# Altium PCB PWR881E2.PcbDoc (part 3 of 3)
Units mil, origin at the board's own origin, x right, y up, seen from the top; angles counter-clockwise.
Board outline 6500 x 3500 mil, 6 copper layers (Top Layer, Signal Layer 1, Signal Layer 2, Signal Layer 3, Signal Layer 4, Bottom Layer), stack 32.4 mil thick; 330 components, 152 nets, 836 pads, 570 vias.
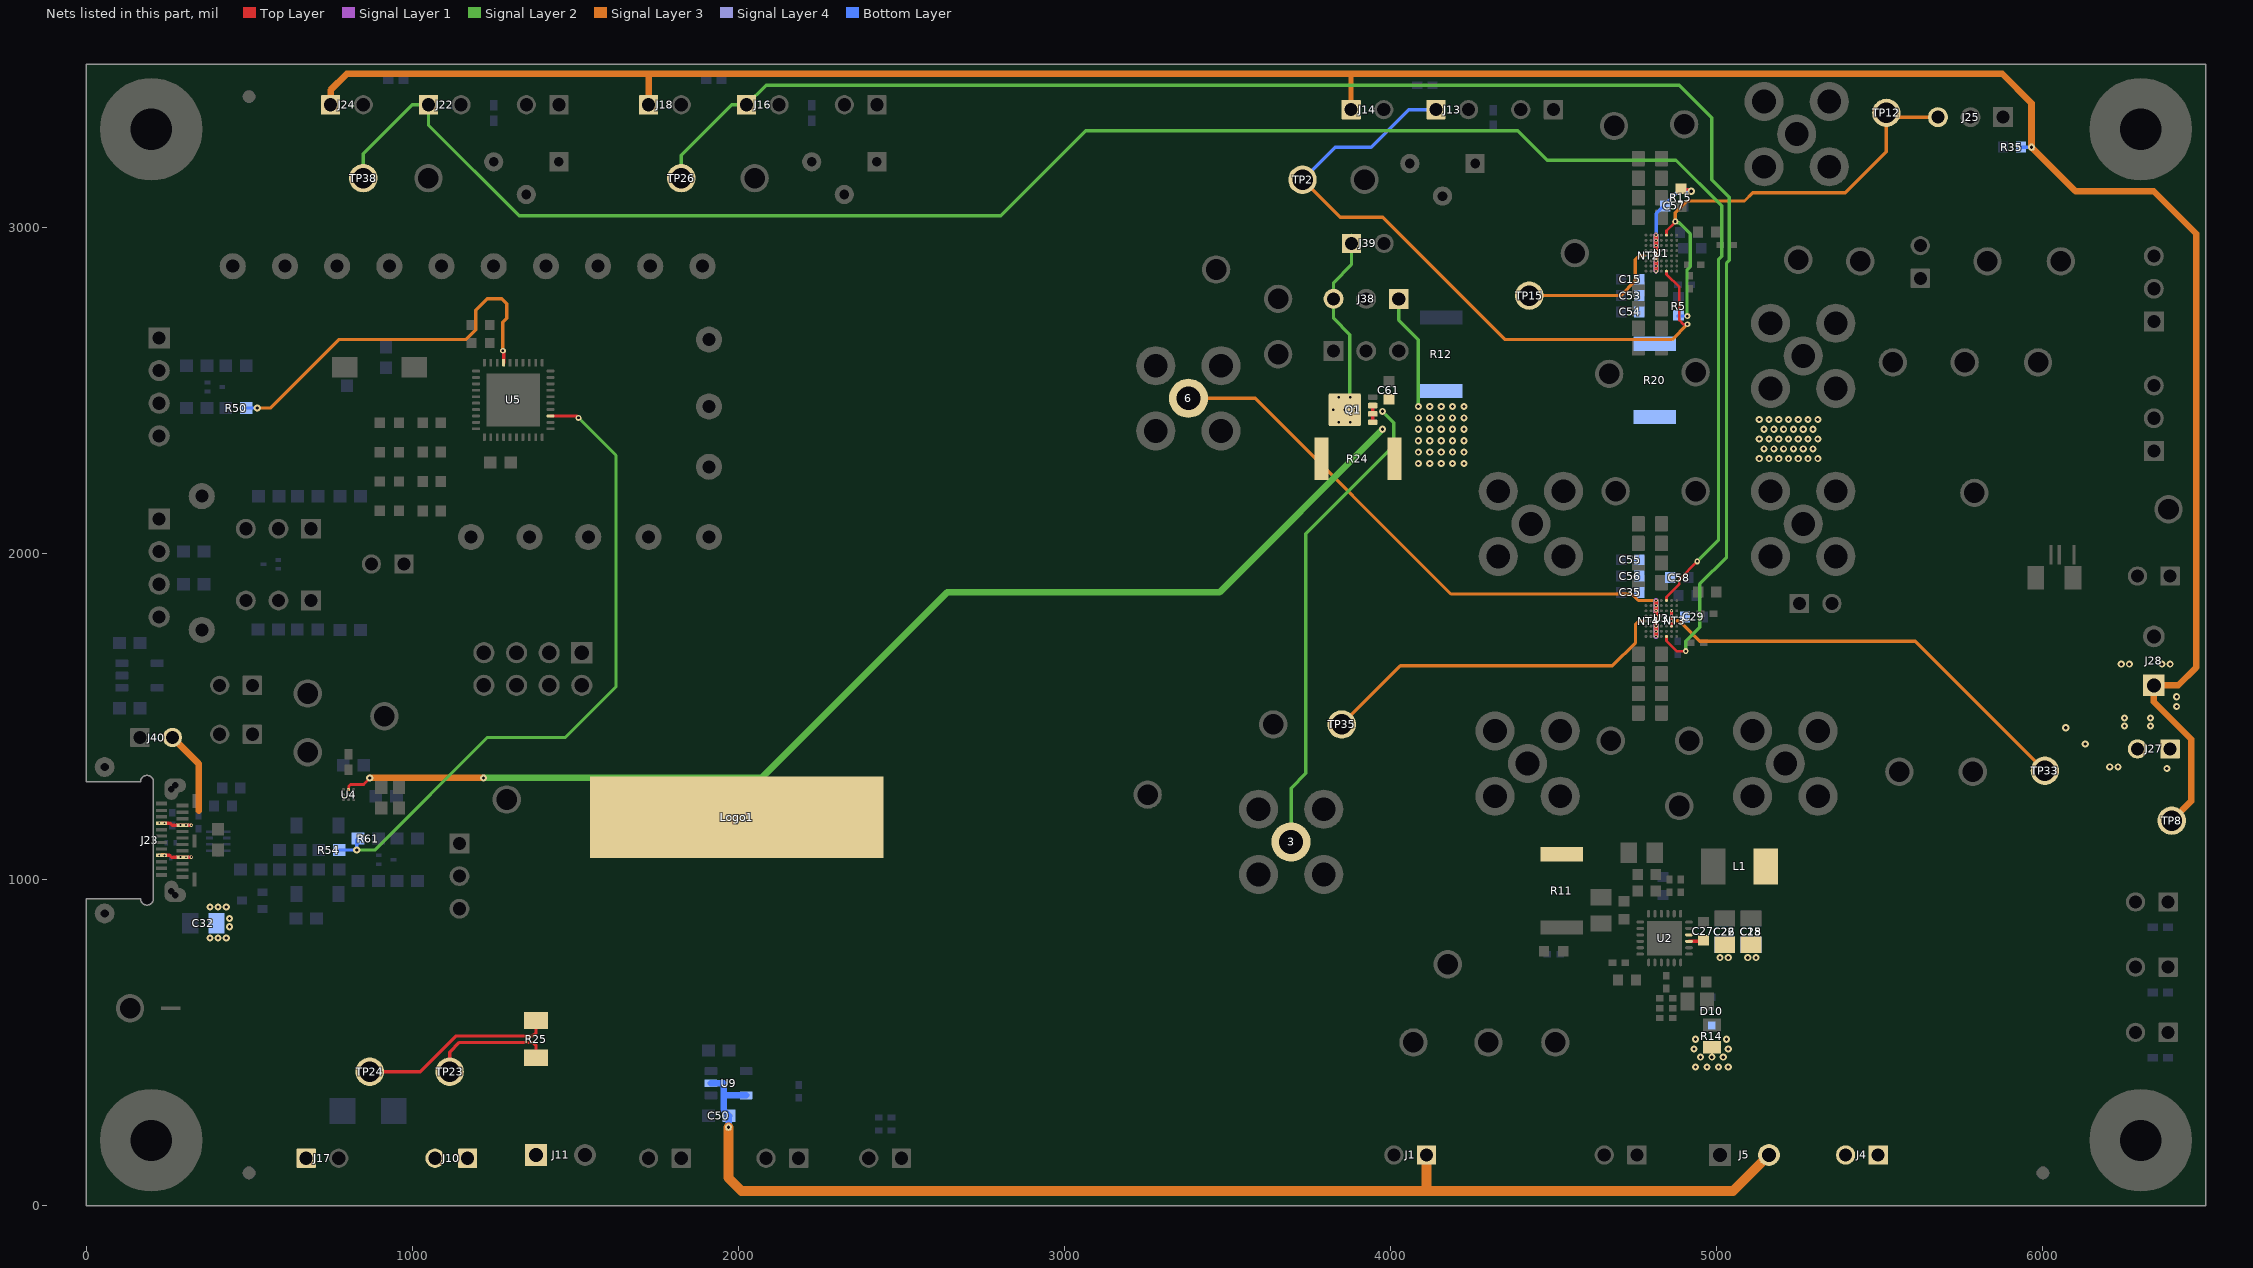
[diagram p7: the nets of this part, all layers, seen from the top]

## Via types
v1: diameter 22, hole 10, Top Layer to Bottom Layer, tented both sides, 399 vias
v2: diameter 10, hole 6, Top Layer to Bottom Layer, tented both sides, 72 vias
v3: diameter 18, hole 8, Top Layer to Bottom Layer, tented both sides, 37 vias
v4: diameter 28, hole 12, Top Layer to Bottom Layer, tented both sides, 36 vias
v5: diameter 19.68, hole 7.87, Top Layer to Bottom Layer, 23 vias
v6: diameter 12, hole 6, Top Layer to Bottom Layer, tented both sides, 2 vias
v7: diameter 19.68, hole 7.87, Top Layer to Bottom Layer, tented both sides, 1 vias

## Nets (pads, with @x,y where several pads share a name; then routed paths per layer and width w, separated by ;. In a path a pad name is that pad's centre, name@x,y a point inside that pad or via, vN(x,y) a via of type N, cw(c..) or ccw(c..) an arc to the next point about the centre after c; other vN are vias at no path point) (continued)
SYNCOUT: J25.3 R5.2 TP12.1 U1.A5 | length 1423.8
  Top Layer w8: U1.A5@4845.75,2975.12 4845.75,2988.75 4868.5,3011.5 v3@4868.5,3017.5
  Signal Layer 2 w10: v3@4869,3017 4876,3017 4880,3013 4885,3013 4919,2979 4919,2879 4909,2869 v3@4909,2727
  Signal Layer 3 w10: v3@4869,3017 4873,3021 4873,3044 4909,3080 5085,3080 5110,3105 5394,3105 5520,3231 5520,3339 5522,3337 J25.3@5678,3337
  Bottom Layer w10: R5.2@4880,2727.44 4880.44,2727 v3(4910,2727)
  other v3: 4873,3017
SYS: C18.1 C22.1 C25.1 C26.1 C27.1 C50.1 J1.1 J4.1 J4.2 J5.2 L1.2 U2.15 U2.16 U9.2 U9.5 | length 3810.9
  Top Layer w10: U2.15@4914.8,810.16 C27.1@4960,810.16
  Signal Layer 3 w30: v1(1970,240) 1970,85 2010,45 4110,45 ; J1.1@4110,155 4110,45 ; J5.2@5160,155 5050,45 4110,45
  Bottom Layer w20: U9.2@1915.87,375 1955,375 1955,337.6 ; v1(1970,240) C50.1@1970,273.5 ; C50.1@1971.5,275 1955,291.5 1955,337.6 ; U9.5@2024.13,337.6 1955,337.6
  other v1: 5010,760 5035,760 5095,760 5120,760
TEST_MCU: R50.1 U5.37 | length 1166.5
  Top Layer w10: U5.37@1280.47,2584.17 v3@1280.47,2621
  Signal Layer 3 w10: v1@525,2440 530,2445 565,2445 775,2655 1165,2655 1195,2685 1195,2745 1230,2780 1275,2780 1290,2765 1290,2720 1278,2708 v3(1278,2621)
  Bottom Layer w10: R50.1@491.5,2445 v1(525,2445)
TSBAT_S: J22.1 TP38.1 U3.A5 | length 5962.2
  Top Layer w8: U3.A5@4845.75,1855.12 4845.75,1865.75 4885,1905 4885,1920 v3(4940,1975)
  Signal Layer 2 w10: TP38.1@850,3150 850,3225 1000,3375 J22.1@1050,3375 1050,3313 1328,3035 2805,3035 3065,3295 4390,3295 4480,3205 4875,3205 5015,3065 5015,2910 5005,2900 5005,2040 v3(4940,1975)
TSBUS_M: J13.1 TP2.1 U1.H5 | length 2097
  Top Layer w8: U1.H5@4845.75,2864.88 4845.75,2855.25 4885,2816 4885,2715 4898,2702 v3(4910,2702)
  Signal Layer 3 w10: TP2.1@3730,3145 3845,3030 3976,3030 4351,2655 4863,2655 v3(4910,2702)
  Bottom Layer w10: TP2.1@3730,3145 3830,3245 3940,3245 4055,3360 J13.1@4139,3360
TSBUS_S: J16.1 TP26.1 U3.H5 | length 5193.7
  Top Layer w8: U3.H5@4845.75,1744.88 4845.75,1731.25 4877,1700 v3(4905,1700)
  Signal Layer 2 w10: TP26.1@1825,3150 1850,3150 1825,3175 1825,3220 1980,3375 J16.1@2025,3375 2085,3435 4885,3435 4985,3335 4985,3145 5038,3092 5038,2898 5030,2890 5030,1988 4948,1906 4948,1773 4905,1730 v3(4905,1700)
TX_MCU: R54.2 R61.1 U5.23 | length 2045.8
  Top Layer w10: U5.23@1424.17,2420.79 1504.21,2420.79 v3@1505,2420
  Signal Layer 2 w10: v1(830,1090) 885,1090 1230,1435 1470,1435 1625,1590 1625,2300 v3(1510,2415)
  Bottom Layer w10: R54.2@776.5,1090 v1(830,1090) 830,1121.5 R61.1@833.5,1125
VBUS_C: C32.1 J17.1 J23.A4 J23.A9 J23.B4 J23.B9 J38.3 J39.1 J40.2 Logo1.0 Q1.5 Q1.6 Q1.7 Q1.8 Q1.9@3859.41,2440 R24.1 R25.1 TP24.1 | length 1601.6
  Top Layer w10: J23.B4@231.3,1073.74 v2(241.3,1073.74) 256.26,1073.74 262.17,1067.83 J23.A9@296.26,1067.83 296.43,1068 v2(323,1068) ; J23.B9@231.3,1172.17 257.83,1172.17 263.74,1166.26 J23.A4@296.26,1166.26 296.52,1166 v2(323,1166) ; TP24.1@870,410 1025,410 1135,520 1370,520 1380,530 R25.1@1380,567.09
  Signal Layer 2 w10: v5@3878.1,2478.39 3875,2481.49 3875,2670 3825,2720 3825,2830 3880,2885 J39.1@3880,2975
  Signal Layer 3 w10: v2(224.54,1073.91) 224.7,1073.74 v2(241.3,1073.74)
  Signal Layer 3 w20: J40.2@265,1435 345,1355 345,1210
  other v1: 380,820 405,820 430,820 440,855 440,880 380,915 405,915 430,915
  other v2: 289.5,1068 306.26,1067.83 289.5,1166.43 306.26,1166.26 224.54,1172.33 241.3,1172.17
  other v5: 3841.61,2401.61 3876.1,2401.61 3858.86,2440 3893.35,2440 3841.61,2478.39 3876.1,2478.39
  other v7: 3824.37,2440
VBUS_CHG: 3.1 C29.2 C61.1 J38.1 NT3.1 Q1.1 Q1.2 Q1.3 R11.2 R12.2 R24.2 U3.C6 U3.D6 U3.E6 U3.F6 U4.A2 | length 5551.4
  Top Layer w8: U4.A2@805,1275.75 805,1285 811,1291 851,1291 v1@870.5,1310.5
  Top Layer w10: Q1.1@3945.04,2401.61 Q1.2@3945.04,2427.2 Q1.3@3945.04,2452.8 ; U3.F6@4861.5,1776.38 v2(4861.5,1792.13) v2(4861.5,1807.87) v2(4861.5,1823.62)
  Signal Layer 2 w10: 3.1@3695,1115 3695,1280 3740,1325 3740,2060 4010,2330 4010,2400 v1(3975,2435) ; J38.1@4025,2780 4025,2715 4085,2655 v1(4085,2450)
  Signal Layer 2 w20: v1(1219,1311) 2071,1311 2640,1880 3475,1880 v1(3975,2380)
  Signal Layer 3 w20: v1(870,1311) v1(1219,1311)
  other v1: 4085,2275 4120,2275 4155,2275 4190,2275 4225,2275 4085,2310 4120,2310 4155,2310 4190,2310 4225,2310 4085,2345 4120,2345 4155,2345 4190,2345 4225,2345 4085,2380 4120,2380 4155,2380 4190,2380 4225,2380 4085,2415 4120,2415 4155,2415 4190,2415 4225,2415 4120,2450 4155,2450 4190,2450 4225,2450
VBUS_CHG_SNS: NT3.2 TP33.1 | length 1318.5
  Signal Layer 3 w10: NT3.2@4878,1793 4885,1793 4948,1730 5609,1730 TP33.1@6006,1333
VBUS_P: J10.1 J10.2 J11.1 R25.2 TP23.1 | length 388.7
  Top Layer w10: TP23.1@1115,400 1115,470 1145,500 1370,500 1380,490 R25.2@1380,452.91
VOUT: 6.1 C35.1 C55.1 C56.1 C58.1 D10.1 J14.1 J18.1 J24.1 J27.1 J27.2 J28.1 NT4.1 R14.2 R20.2 R35.1 TP8.1 U3.A3 U3.B3 U3.C3 U3.D3 U3.E3 U3.F3 U3.G3 U3.H3 | length 10617.7
  Top Layer w10: v2(4814.25,1744.88) v2(4814.25,1760.63) v2(4814.25,1776.38) v2(4814.25,1792.13) v2(4814.25,1807.87) v2(4814.25,1823.62) v2(4814.25,1839.37) v2(4814.25,1855.12)
  Signal Layer 1 w15: v2(4814.25,1744.88) v2(4814.25,1760.63) v2(4814.25,1776.38) v2(4814.25,1792.13) v2(4814.25,1807.87) v2(4814.25,1823.62) v2(4814.25,1839.37) v2(4814.25,1855.12)
  Signal Layer 2 w15: v2(4814.25,1744.88) v2(4814.25,1760.63) v2(4814.25,1776.38) v2(4814.25,1792.13) v2(4814.25,1807.87) v2(4814.25,1823.62) v2(4814.25,1839.37) v2(4814.25,1855.12)
  Signal Layer 3 w10: 6.1@3380,2475 3585,2475 4185,1875 4740,1875 4759.88,1855.12 v2(4814.25,1855.12) ; 3879,3469 3880,3470
  Signal Layer 3 w15: J14.1@3879,3360 3879,3469 ; v2(4814.25,1744.88) v2(4814.25,1760.63) v2(4814.25,1776.38) v2(4814.25,1792.13) v2(4814.25,1807.87) v2(4814.25,1823.62) v2(4814.25,1839.37) v2(4814.25,1855.12)
  Signal Layer 3 w20: J24.1@750,3375 750,3420 800,3470 1725,3470 ; J18.1@1725,3375 1725,3470 ; J28.1@6330,1585 6340,1585 6340,1545 6455,1430 6455,1240 TP8.1@6395,1180 ; J28.1@6340,1595 6415,1595 6470,1650 6470,2980 ; 6462.5,2987.5 6340,3110 6100,3110 v1(5965,3245) 5965,3380 5875,3470 3880,3470 1725,3470
  Signal Layer 4 w15: v2(4814.25,1744.88) v2(4814.25,1760.63) v2(4814.25,1776.38) v2(4814.25,1792.13) v2(4814.25,1807.87) v2(4814.25,1823.62) v2(4814.25,1839.37) v2(4814.25,1855.12)
  Bottom Layer w10: v2(4814.25,1744.88) v2(4814.25,1760.63) v2(4814.25,1776.38) v2(4814.25,1792.13) v2(4814.25,1807.87) v2(4814.25,1823.62) v2(4814.25,1839.37) v2(4814.25,1855.12) ; R35.1@5932.56,3245 v1(5965,3245)
  other v1: 4935,425 4970,425 5005,425 5035,425 4950,455 4985,455 5020,455 4930,480 5035,480 4935,510 5030,510 6380,1340 6205,1345 6230,1345 6130,1415 6070,1465 6250,1470 6330,1470 6250,1495 6330,1495 6410,1530 6410,1560 6240,1660 6265,1660 6365,1660 6390,1660 5130,2290 5160,2290 5190,2290 5220,2290 5250,2290 5280,2290 5310,2290 5145,2320 5175,2320 5205,2320 5235,2320 5265,2320 5295,2320 5130,2350 5160,2350 5190,2350 5220,2350 5250,2350 5280,2350 5310,2350 5145,2380 5175,2380 5205,2380 5235,2380 5265,2380 5295,2380 5130,2410 5160,2410 5190,2410 5220,2410 5250,2410 5280,2410 5310,2410
VOUT_M: C15.1 C53.1 C54.1 C57.1 NT2.1 R15.2 R20.1 U1.A3 U1.B3 U1.C3 U1.D3 U1.E3 U1.F3 U1.G3 U1.H3 | length 897.2
  Top Layer w10: v2(4814.25,2864.88) v2(4814.25,2880.63) v2(4814.25,2896.38) v2(4814.25,2912.13) v2(4814.25,2927.87) v2(4814.25,2943.62) v2(4814.25,2959.37) v2(4814.25,2975.12) ; R15.2@4890,3117.56 4892.56,3115 v1@4922,3115
  Signal Layer 1 w15: v2(4814.25,2864.88) v2(4814.25,2880.63) v2(4814.25,2896.38) v2(4814.25,2912.13) v2(4814.25,2927.87) v2(4814.25,2943.62) v2(4814.25,2959.37) v2(4814.25,2975.12)
  Signal Layer 2 w15: v2(4814.25,2864.88) v2(4814.25,2880.63) v2(4814.25,2896.38) v2(4814.25,2912.13) v2(4814.25,2927.87) v2(4814.25,2943.62) v2(4814.25,2959.37) v2(4814.25,2975.12)
  Signal Layer 3 w15: v2(4814.25,2864.88) v2(4814.25,2880.63) v2(4814.25,2896.38) v2(4814.25,2912.13) v2(4814.25,2927.87) v2(4814.25,2943.62) v2(4814.25,2959.37) v2(4814.25,2975.12)
  Signal Layer 4 w15: v2(4814.25,2864.88) v2(4814.25,2880.63) v2(4814.25,2896.38) v2(4814.25,2912.13) v2(4814.25,2927.87) v2(4814.25,2943.62) v2(4814.25,2959.37) v2(4814.25,2975.12)
  Bottom Layer w10: v2(4814.25,2864.88) v2(4814.25,2880.63) v2(4814.25,2896.38) v2(4814.25,2912.13) v2(4814.25,2927.87) v2(4814.25,2943.62) v2(4814.25,2959.37) v2(4814.25,2975.12) 4814.25,3041.81 4882.44,3110 v1(4922,3110)
VOUT_SNS_M: NT2.2 TP15.1 | length 442.7
  Signal Layer 3 w10: TP15.1@4425,2785 4430,2790 4705,2790 4750,2835 4750,2900 4762,2912 NT2.2@4777,2912
VOUT_SNS_S: NT4.2 TP35.1 | length 1091.1
  Signal Layer 3 w10: TP35.1@3850,1475 4030,1655 4680,1655 4751,1726 4751,1782 4761,1792 NT4.2@4777,1792
pads on no net: FID1.1 FID2.1 FID3.1 FID4.1 FID5.1 FID6.1 H1.0 H2.1 H3.0 H4.1 H5.0 H6.1 H7.0 H8.1 J23.1 J23.2 J23.3 J23.A2 J23.A3 J23.A8 J23.A10 J23.A11 J23.B2 J23.B3 J23.B8 J23.B10 J23.B11 J23.H1 J23.H2 J23.H3 J23.H4 J23.H5 J23.H6 J36.4 LBL1.0 Q1.9@3838.74,2401.61 Q1.9@3838.74,2427.2 Q1.9@3838.74,2452.8 Q1.9@3838.74,2478.39 Q1.9@3858.86,2413.92 Q1.9@3858.86,2466.08 Q1.9@3872.11,2440 Q1.9@3893.35,2413.92 Q1.9@3893.35,2466.08 R29.1 R32.1 R38.1 SH-J1.0 SH-J6.0 SH-J9.0 SH-J16.0 SH-J17.0 SH-J18.0 SH-J19.0 SH-J20p.0 SH-J20s.0 SH-J21p.0 SH-J21s.0 SH-J22.0 SH-J24.0 SH-J26.0 SH-J30.0 SH-J31.0 SH-J37p.0 SH-J37s.0 SH-J38p.0 SH-J38s.0 SH-J39.0 SH-J40.0 SH-J41.0 SH-J42.0 SH-J43.0 U5.41@1256.06,2416.06 U5.41@1256.06,2470 U5.41@1256.06,2523.94 U5.41@1310,2416.06 U5.41@1310,2470 U5.41@1310,2523.94 U5.41@1363.94,2416.06 U5.41@1363.94,2470 U5.41@1363.94,2523.94

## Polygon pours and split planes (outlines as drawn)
GND on Top Layer "TOP_LAYER_GND_P221" (solid, remove dead copper, pour order 352): 25,3475 6475,3475 6475,25 25,25
3V3_SYS on Top Layer "Top Layer-No Net" (solid, remove dead copper, pour order 335): 1235,2575 1235,2615 1235,2625 1230,2630 1225,2635 1225,2715 1225,2750 1235,2760 1245,2760 1260,2760 1265,2755 1265,2715 1265,2575
VBUS_P on Top Layer "Top Layer-No Net" (solid, remove dead copper, pour order 347): 1255,480 1255,415 1210,370 1015,175 1015,90 1450,90 1450,440 1450,480
VBUS_C on Top Layer "Top Layer-No Net" (solid, remove dead copper, pour order 351): 1415,540 1070,540 910,540 725,355 725,110 595,110 410,295 340,365 340,655 340,820 340,940 460,940 520,940 755,940 792.5,977.5 1167.5,977.5 2480,2290 3535,2290 3575,2330 3575,2500 3915,2500 3915,1880 3385,1350 3005,1350 2195,540
VBUS_CHG on Top Layer "Top Layer-No Net" (solid, remove dead copper, pour order 349): 4260,2500 3930,2500 3930,1045 4055,920 4595,920 4595,965 4595,1117.5 4312.5,1117.5 4260,1170
NetC2_1 on Top Layer "Top Layer-No Net" (solid, remove dead copper, pour order 336): 4785,1110 4785,910 4795,900 4820,900 4825,905 4835,915 4835,1110
NetC11_2 on Top Layer "Top Layer-No Net" (solid, remove dead copper, pour order 342): 4865,890 4865,915 4870,920 4875,925 4875,945 4875,975 4900,975 4910,985 4920,995 4920,1010 4920,1065 4950,1095 5030,1095 5030,985 5000,985 4905,890
SYS on Top Layer "Top Layer-No Net" (solid, remove dead copper, pour order 348): 4910,815 4910,835 4955,835 4975,835 4980,840 5000,840 5140,840 5145,845 5150,850 5150,860 5150,900 5150,925 5130,945 5110,965 5110,1095 5220,1095 5257.5,1057.5 5310,1005 5310,770 5535,545 5535,200 5535,140 5535,105 5165,105 5065,105 5065,240 5065,525 5055,535 5030,560 5030,575 5030,705 4935,800 4930,805 4910,805
NetC10_1 on Top Layer "Top Layer-No Net" (solid, remove dead copper, pour order 341): 4905,795 4930,795 5020,705 5020,675 5020,535 4940,535 4940,720 4905,755
Net1_1 on Top Layer "Top Layer-No Net" (solid, remove dead copper, pour order 339): 4810,2915.45 4860,2915.45 4860,2605 4800,2605 4800,2845 4810,2855
NetC13_2 on Top Layer "Top Layer-No Net" (solid, remove dead copper, pour order 344): 4730,2880.45 4730,2603.8 4805,2603.8 4805,2910.45 4805,2915.45 4765,2915.45
NetC14_2 on Top Layer "Top Layer-No Net" (solid, remove dead copper, pour order 343): 4730,3235 4730,2925 4805.42,2925 4800,3186.2 4800,3235
Net2_1 on Top Layer "Top Layer-No Net" (solid, remove dead copper, pour order 337): 4800,3235 4860,3235 4860,2925 4810,2925 4810,3015 4800,3025
Net5_1 on Top Layer "Top Layer-No Net" (solid, remove dead copper, pour order 340): 4800,2119 4860,2119 4860,1805 4840,1805 4810,1805 4810,1870 4800,1880
Net8_1 on Top Layer "Top Layer-No Net" (solid, remove dead copper, pour order 346): 4730,2119 4730,1805 4805,1805 4805,2045 4805,2119
Net7_1 on Top Layer "Top Layer-No Net" (solid, remove dead copper, pour order 345): 4730,1795 4730,1485 4805,1485 4805,1790 4805,1795 4765,1795
Net4_1 on Top Layer "Top Layer-No Net" (solid, remove dead copper, pour order 338): 4810,1795 4860,1795 4860,1485 4800,1485 4800,1715 4810,1725
VOUT on Top Layer "Top Layer-No Net" (solid, remove dead copper, pour order 350): 5663.5,2435 5735,2363.5 5735,1740 5785,1690 6055,1690 6430,1690 6430,1325 6105,1325 6040,1390 5580,1390 5530,1440 5435,1535 5435,1960 5435,2225 5405,2255 5400,2260 5100,2260 5100,2435
VBUS_C on Signal Layer 3 "Top Layer-No Net" (solid, remove dead copper, pour order 354): 215,1225 360,1225 360,1195 494,1061 494,805.13 360,805.13 320,845.13 320,960 320,1000 310,1010 215,1010
GND on Bottom Layer "BOTTOM_LAYER_GND_P223" (solid, remove dead copper, pour order 362): 25,3475 6475,3475 6475,25 25,25
VOUT on Bottom Layer "Top Layer-No Net" (solid, remove dead copper, pour order 361): 6430,1680 6225,1680 5717.5,1172.5 5572.5,1172.5 4920,520 4920,500 4920,445 4920,410.81 5045,410.81 5079.19,445 5295,445 5565,445 6430,1310
GND on Bottom Layer "BOTTOM_LAYER_GND_P219" (solid, remove dead copper, pour order 356): 4920,1895 4980,1895 5025,1850 5025,1840 4975,1790 4940,1790 4940,1825 4920,1845 4920,1855
VOUT_M on Bottom Layer "Top Layer-No Net" (solid, remove dead copper, pour order 357): 4835,2990 4745,2990 4745,2840 4745,2800 4745,2615 4880,2615 4880,2795 4855,2820 4855,2855 4845,2865 4845,2895 4835,2905
VOUT on Bottom Layer "Top Layer-No Net" (solid, remove dead copper, pour order 358): 4745,2444.8 5335,2445.15 5335,2255 4925,2255 4875.2,2205.2 4875.2,1905.2 4835,1865 4835,1735 4745,1735 4745,1870
VBUS_CHG on Bottom Layer "Top Layer-No Net" (solid, remove dead copper, pour order 360): 4885,1725 4565,1725 4260,2030 4260,2525 4040,2525 4040,1760 4295,1505 5100,1505 5100,1745 5065,1780 4935,1780 4930,1785 4930,1830 4860,1830 4858,1828 4858,1788 4872,1788 4880,1780 4885,1775
NetC5_2 on Bottom Layer "Top Layer-No Net" (solid, remove dead copper, pour order 359): 4885.39,2835 5030.39,2835 5090.39,2895 5090.39,3165 4965.39,3290 4430,3290 4070,2930 4070,2695 4270,2695 4270,2755 4510,2995 4730,2995 4860,3125 4920.39,3125 4920.39,3090 4955.39,3090 4980.39,3065 4980.39,2890 4935.39,2890 4925.39,2900 4925.39,2950 4856.39,2950 4856.39,2908 4885.39,2900 4885.39,2875 4885.39,2865
GND on Signal Layer 1 "SIGNAL_LAYER_1_GND_P195" (solid, remove dead copper, pour order 353): 25,3475 6475,3475 6475,25 25,25
GND on Signal Layer 4 "SIGNAL_LAYER_4_AGND_P206" (solid, remove dead copper, pour order 355): 25,3475 6475,3475 6475,25 25,25

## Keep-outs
Keep-Out Layer:
  lines w10: -5,0 ccw(c0,0) 0,-5 ; -5,0 ccw(c0,0) 0,-5 ; -5,0 -5,940.87 ; -5,940.87 cw(c0,940.87) 0,945.87 ; -5,940.87 cw(c0,940.87) 0,945.87 ; -5,1299.13 ccw(c0,1299.13) 0,1294.13 ; -5,1299.13 ccw(c0,1299.13) 0,1294.13 ; -5,1299.13 -5,3500 ; -5,3500 cw(c0,3500) 0,3505 ; -5,3500 cw(c0,3500) 0,3505 ; 0,-5 6500,-5 ; 0,945.87 167.32,945.87 ; 0,1294.13 167.32,1294.13 ; 0,3505 6500,3505 ; 167.32,945.87 cw(c167.32,940.87) 172.32,940.87 ; 167.32,945.87 cw(c167.32,940.87) 172.32,940.87 ; 167.32,1294.13 ccw(c167.32,1299.13) 172.32,1299.13 ; 167.32,1294.13 ccw(c167.32,1299.13) 172.32,1299.13 ; 172.32,940.87 172.32,937.95 174.56,932.55 178.69,928.42 184.09,926.18 189.93,926.18 195.33,928.42 199.46,932.55 201.69,937.95 201.69,940.87 ; 172.32,1299.13 172.32,1302.05 174.56,1307.45 178.69,1311.58 184.09,1313.82 189.93,1313.82 195.33,1311.58 199.46,1307.45 201.69,1302.05 201.69,1299.13 201.69,1120 201.69,940.87 ; 201.69,940.87 ccw(c206.69,940.87) 201.69,940.87 ; 201.69,940.87 ccw(c206.69,940.87) 201.69,940.87 ; 6500,-5 ccw(c6500,0) 6505,0 ; 6500,-5 ccw(c6500,0) 6505,0 ; 6500,3505 cw(c6500,3500) 6505,3500 ; 6500,3505 cw(c6500,3500) 6505,3500 ; 6505,0 6505,3500
  text ".Layer_Name" at 577,-858.49 h60

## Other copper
Top Layer:
  rectangle net AGND: 1220,2220 1260,2285
  rectangle net NetC1_1: 4460,825 4710,890
  rectangle net GND: 4885,540 4930,655
  rectangle net GND: 855,1185 1005,1245
  rectangle net GND: 795,1185 1005,1215
  rectangle net GND: 4610,920 4770,1115
  rectangle net GND: 4905,845 4970,880
  rectangle net GND: 4990,860 5130,930
  rectangle net GND: 4940,855 5135,910
  rectangle net GND: 4665,1739 4785,1859
  rectangle net GND: 4670,2859 4785,2978
  rectangle net VOUT: 4920,410 5045,520
  rectangle net NetJ28_2: 6070,1705 6430,1965
  rectangle net AGND: 1140,2584.17 1195.83,2715
  rectangle net GND: 290,1220 315,1250
  rectangle net GND: 290,980 315,1007.8
  rectangle net NetC1_1: 4460,825 4560,910
  pour cut-out: 1460,535 1460,480 1455,480 1455,535
  pour cut-out: 5190,1150 5190,1100 5110,1100 5105,1095 5105,960 5135,930 5120,930 4960,930 4960,935 5000,975 5030,975 5035,980 5035,1095 5030,1100 4950,1100 4950,1150
  pour cut-out: 6010,1985 6068,1985 6068,1969.91 6068,1889 6003,1889 6003,1962 6010,1969
  pour cut-out: 4450.58,821.1 4450,820.52 4450,805 4455,805 4455,820
  text ".Layer_Name" at 577,-858.49 h60
Signal Layer 1:
  text ".Layer_Name" at 577,-858.49 h60
Signal Layer 2:
  text ".Layer_Name" at 577,-858.49 h60
Signal Layer 3:
  rectangle net AGND: 1225,2385 1395,2555
  text ".Layer_Name" at 577,-858.49 h60
Signal Layer 4:
  text ".Layer_Name" at 577,-858.49 h60
Bottom Layer:
  rectangle net VBUS_C: 3810,2391.92 3914.8,2505
  rectangle net GND: 4933,2897 4968,3000
  rectangle net GND: 265,810 345,910
  rectangle net GND: 4990,855 5140,930
  rectangle net GND: 895,220 990,330
  rectangle net GND: 705,860 790,975
  rectangle net NetC5_2: 4857,2908 4888,2948
  rectangle net VBUS_CHG: 4858,1788 4905,1828
  rectangle net NetD2_1: 740,115 830,330
  rectangle net VBUS_C: 370,810 450,925
  rectangle net SYS: 4995,750 5130,820
  rectangle net GND: 4930,2968 4970,3061
  rectangle net AGND: 1215,2375 1405,2565
  text ".Layer_Name" at 577,-858.49 h60

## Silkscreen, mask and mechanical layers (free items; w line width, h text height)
Top Overlay:
  region: 2465,1045 2165,1045 2165,945 2465,945
  text "SYNCIN" at 5680,3225 h60
  text "VOUT" at 5910,3225 h60
  text "INT_M" at 5730,2900 h50 r90
  text "GND" at 6160,2890 h60
  text "SRP" at 6160,2690 h60
  text "3V3_SYS" at 5730,2685 h50 r90
  text "GND" at 6160,2495 h60
  text "SRN" at 6160,2295 h60
  text "BATN" at 6270,2000 h60
  text "3V3_SYS" at 765,1875 h40
  text "I2C" at 955,1875 h40
  text "3V3_SYS" at 5110,1745 h50
  text "INT_S" at 5345,1745 h50
  text "BATN" at 6035,1720 h60
  text "VOUT" at 6035,1580 h60
  text "LDO_U8" at 55,1505 h40
  text "VBUS_C" at 220,1505 h40
  text "VOUT" at 6270,1285 h60
  text "TX_MCU" at 1215,1090 h60
  text "RX_MCU" at 1220,990 h60
  text "'.PRJ_Number'.PCB_Rev-" at 1605,965 h108.27
  text "GND" at 1220,890 h60
  text "GND" at 4950,330 h60
  text "SYS" at 5100,330 h60
  text "VBUS" at 1310,325 h60
  text "GND" at 1485,325 h60
  text "GND" at 4645,235 h60
  text "SYS" at 5390,235 h60
  text "GND" at 2305,230 h60
  text "/CD" at 2470,230 h60
  text "ZENER" at 640,225 h60
  text "VBUS" at 1055,225 h60
  text "GND" at 1720,225 h60
  text "GND" at 1995,225 h60
  text "OTG" at 2140,225 h60
  text ".Layer_Name" at 577,-858.49 h60
Bottom Overlay:
  text ".Layer_Name" at 577,-858.49 h60
Top Paste:
  text ".Layer_Name" at 577,-858.49 h60
Bottom Paste:
  text ".Layer_Name" at 577,-858.49 h60
Top Solder:
  text ".Layer_Name" at 577,-858.49 h60
  text ".Layer_Name" at 577,-858.49 h60
Bottom Solder:
  text ".Layer_Name" at 577,-858.49 h60
Drill Guide:
  text ".Layer_Name" at 577,-858.49 h60
M1 Board Outline:
  lines w10: 0,822.27 0,0 6500,0 6500,3500 0,3500 0,1388.6
  text ".Layer_Name" at 577,-858.49 h60
M2 Board Dimensions:
  rectangle: 0,-275 125,-150
  rectangle: 125,-400 500,-275
  lines w7: 0,-275 1000,-275 ; 125,-400 125,-150 ; 250,-400 250,-150 ; 500,-400 500,-150 ; 750,-400 750,-150 ; 0,-400 1000,-400 1000,-150 0,-150 0,-400
  text ".Layer_Name" at 577,-858.49 h60
M3 3D STEP Top:
  text ".Layer_Name" at 577,-858.49 h60
M4 3D STEP Bottom:
  text ".Layer_Name" at 577,-858.49 h60
M5 Assembly Top:
  lines w10: -292,-930.17 6308,-930.17 ; -292,-726.83 6310,-726.83 ; -292,-523.5 -292,-1133.5 3713,-1133.5 6310,-1133.5 6310,-523.5 -291.5,-523.5 -291.5,-1133.5 1284,-1133.5 ; 2173,-1133.5 2173,-523.5 ; 3440,-726.83 3440,-523.5 ; 4280,-726.83 4280,-523.5 ; 4902,-1140 4902,-937.17
  text "COMPONENTS MARKED 'DNP' SHOULD NOT BE POPULATED." at 1153.5,-318.5 h60
  text "ASSEMBLY VARIANT:" at 1153,-434 h60
  text ".VariantName" at 2189,-434 h60
  text "PCB VIEWED FROM TOP SIDE" at -228.5,-655.67 h60
  text "BOARD #:" at 2248,-655.67 h60
  text ".PRJ_Number" at 2793.5,-655.67 h60
  text "REV:" at 3638,-655.67 h60
  text ".PCB_Rev" at 3929.5,-655.67 h60
  text "SVN REV:" at 4476,-655.67 h60
  text ".VersionControl_RevNumber" at 4982,-655.67 h60
  text "TID #:" at 2248,-859 h60
  text ".TID" at 2793.5,-859 h60
  text "PLOT NAME =" at -228.5,-1064.34 h60
  text ".plot_File_Name" at 577,-1064.34 h60
  text "GENERATED    :" at 2250,-1064.34 h60
  text ".Print_Date" at 3119.5,-1064.34 h60
  text ".Print_Time" at 3848.5,-1064.34 h60
  text "TEXAS INSTRUMENTS" at 5113,-1064.34 h60
M6 Assembly Bottom:
  lines w10: -292.5,-727.33 6309.5,-727.33 ; -290.5,-930.67 6309.5,-930.67 ; 1115.5,-1140.5 1115.5,-937.67 ; 1737.5,-727.33 1737.5,-524 ; 2577.5,-727.33 2577.5,-524 ; 3844.5,-1134 3844.5,-524 ; 4733.5,-1134 6309,-1134 6309,-524 -292.5,-524 -292.5,-1134 2304.5,-1134 6309.5,-1134 6309.5,-524
  text "COMPONENTS MARKED 'DNP' SHOULD NOT BE POPULATED." at 6102,-318 h60
  text ".VariantName" at 5058,-434 h60
  text "ASSEMBLY VARIANT:" at 6097,-434 h60
  text ".VersionControl_RevNumber" at 1035.5,-656.17 h60
  text "SVN REV:" at 1541.5,-656.17 h60
  text ".PCB_Rev" at 2088,-656.17 h60
  text "REV:" at 2379.5,-656.17 h60
  text ".PRJ_Number" at 3224,-656.17 h60
  text "BOARD #:" at 3769.5,-656.17 h60
  text "PCB VIEWED FROM BOTTOM SIDE" at 6246,-656.17 h60
  text ".TID" at 3224,-859.5 h60
  text "TID #:" at 3769.5,-859.5 h60
  text "TEXAS INSTRUMENTS" at 904.5,-1064.84 h60
  text ".Print_Time" at 2169,-1064.84 h60
  text ".Print_Date" at 2898,-1064.84 h60
  text "GENERATED    :" at 3767.5,-1064.84 h60
  text ".plot_File_Name" at 5440.5,-1064.84 h60
  text "PLOT NAME =" at 6246,-1064.84 h60
M7 LPKF Text Top:
  region: 2845,0 cw(c5267.32,1756.94) 2835,3500 3855,3500 ccw(c5276.35,1754.05) 3865,0
  lines w10: 2835,3500 ccw(c5267.32,1756.94) 2845,0 3865,0 cw(c5276.35,1754.05) 3855,3500 2835,3500
M8 LPKF Text Bottom:
  circle w750: c5275,1755 r2625
M9 Title Sheet:
  drawing of 57 lines, arcs and shapes, not listed
  text "1" at 739.84,8036.5 h70
  text "2" at 3235.5,8036.5 h70
  text "3" at 5724.84,8036.5 h70
  text "4" at 8231.51,8036.5 h70
  text "5" at 10730.5,8036.5 h70
  text "6" at 13235.5,8036.5 h70
  text "A" at -416.5,6893.5 h70
  text "A" at 14383.5,6893.5 h70
  text "B" at -416.5,4513.5 h70
  text "B" at 14383.5,4513.5 h70
  text "C" at -416.5,2138.5 h70
  text "C" at 14383.5,2138.5 h70
  text "PROJECT TITLE:" at 11343.5,277.5 h45
  text ".PRJ_Title" at 11393.5,144.17 h70
  text "DESIGNED FOR:" at 11343.5,-23.5 h45
  text ".PRJ_Customer" at 11393.5,-163.5 h70
  text "D" at -416.5,-231.5 h70
  text "D" at 14383.5,-231.5 h70
  text "FILE NAME:" at 11343.5,-323.5 h45
  text ".PCB_File_Name_No_Path" at 11393.5,-443.5 h70
  text "Texas Instruments (TI) and/or its licensors do not warrant the accuracy or completeness of this specification" at 6374,-605.34 h45
  text "ENGINEER:" at 11343.5,-613.5 h45
  text "LAYOUT BY:" at 12848.5,-613.5 h45
  text "or any information contained therein. TI and/or its licensors do not warrant that this design will meet" at 6329.01,-718 h45
  text ".PRJ_Engineer" at 11393.5,-768.49 h70
  text ".PCB_Layout" at 12899,-768.49 h70
  text "the specifications, will be suitable for your application or fit for any particular purpose, or will operate in" at 6329.01,-830.67 h45
  text ".Layer_Name" at 577,-858.49 h60
  text "ALTIUM DESIGNER VERSION:" at 12848.5,-923.5 h45
  text "an implementation. TI and/or its licensors do not warrant that the design is production worthy. You should" at 6329.01,-943.33 h45
  text "completely validate and test your design implementation to confirm the system functionality for your application." at 6374,-1056 h45
  text ".print_Scale" at 11393.5,-1056.83 h70
  text ".Application_BuildNumber" at 12899,-1056.83 h70
  text "1" at 739.84,-1263.5 h70
  text "2" at 3235.5,-1263.5 h70
  text "3" at 5724.84,-1263.5 h70
  text "4" at 8231.51,-1263.5 h70
  text "5" at 10730.5,-1263.5 h70
  text "6" at 13235.5,-1263.5 h70
M10 Fab Notes:
  drawing of 173 lines, arcs and shapes, not listed
  text "DESIGN INFORMATION" at 12378.02,6201 h60
  text "MIN. TRACK WIDTH:" at 11733.46,6021 h60
  text "8" at 12829.7,6021 h60
  text "MIL" at 12984.46,6021 h60
  text "MIN. CLEARANCE:" at 11733.46,5889 h60
  text "5.7" at 12769.7,5889 h60
  text "MIL" at 12984.46,5889 h60
  text "MIN. VIA PAD SIZE:" at 11733.46,5757 h60
  text "10" at 12799.71,5757 h60
  text "MIL" at 12984.46,5757 h60
  text "0.05mm (2MIL)" at 12428.46,5615.29 h60
  text "MINIMUM ANNULAR RING" at 11404.23,5611 h60
  text "EXTERNAL" at 13136.46,5611 h60
  text "PER" at 11604.23,5493 h60
  text "IPC-D-275 CLASS 2 LEVEL C" at 11824.23,5493 h60
  text "MIL, HOLES" at 13312.46,5380.71 h60
  text "+/-" at 12920,5380 h60
  text "+/-" at 13774,5380 h60
  text "REGISTRATION TOLERANCES:" at 11404.23,5375 h60
  text "METAL" at 12604,5375 h60
  text "5" at 13180.2,5375 h60
  text "3" at 14013.2,5375 h60
  text "MIL" at 14129.46,5375 h60
  text "+/-" at 13774,5262 h60
  text "HOLE SIZE TOLERANCE (UNLESS OTHERWISE SPECIFIED):" at 11404.23,5257 h60
  text "3" at 14013.2,5257 h60
  text "MIL" at 14129.46,5257 h60
  text "MATERIAL:" at 11329.46,5047.54 h60
  text "FR-4 High Tg" at 12315.9,4907.21 h60
  text "FR-408" at 11750.46,4898.64 h60
  text "OTHER" at 13238.46,4898.64 h60
  text "X" at 12161,4895 h60
  text "31 MIL (0.8mm) +/-10%" at 12070.56,4735.92 h60
  text "THICKNESS:" at 11404.23,4731.64 h60
  text "X" at 11942.4,4731.64 h60
  text "OTHER" at 13355.46,4731.64 h60
  text "TOLERANCE:" at 11404.23,4573.64 h60
  text "X" at 12243.53,4573.64 h60
  text "ANSI IPC-6012 TYPE 3 CLASS 2" at 12430.48,4573.64 h60
  text "OTHER +/-" at 12430.46,4417.64 h60
  text "BOW & TWIST:" at 11404.23,4260.64 h60
  text "X" at 12243.53,4260.64 h60
  text "ANSI IPC-6012 TYPE 3 CLASS 2" at 12430.48,4260.64 h60
  text "All 6 MIL-holed vias must be filled and plated over" at 560,4240 h60
  text "OTHER +/-" at 12430.46,4102.13 h60
  text "DRILLING:" at 11329.46,3963.64 h60
  text "REFERENCE:" at 11404.23,3846.64 h60
  text "X" at 12052.46,3846.64 h60
  text "AS SHOWN" at 12239.46,3846.64 h60
  text "X" at 12953.46,3846.64 h60
  text "NC_DRILL FILES" at 13090.46,3846.64 h60
  text "PTH COPPER THICKNESS:" at 11404.23,3688.64 h60
  text "X" at 12534.46,3688.64 h60
  text "20-30 um" at 12671.46,3688.64 h60
  text "OTHER" at 13388.46,3688.64 h60
  text "BOARD FINISH:" at 11329.46,3529.64 h60
  text "SILKSCREEN:" at 11484.68,3411.64 h60
  text "X" at 12433.46,3411.64 h60
  text "TOP" at 12559.46,3411.64 h60
  text "X" at 12943.46,3411.64 h60
  text "BOTTOM" at 13070.46,3411.64 h60
  text "SILKSCREEN COLOR:" at 11484.68,3244.64 h60
  text "X" at 12432.42,3244.64 h60
  text "WHITE" at 12559.46,3244.64 h60
  text "OTHER" at 13070.46,3244.64 h60
  text "X" at 12563.42,3085.44 h60
  text "GREEN" at 12690.46,3085.44 h60
  text "OTHER" at 13308.46,3085.44 h60
  text "SOLDER RESIST COLOR:" at 11484.68,3074.64 h60
  text "MATTE" at 12690.46,2915.44 h60
  text "X" at 13160,2915 h60
  text "SEMI-GLOSS" at 13308,2914.8 h60
  text "IMMERSION GOLD (ENIG)" at 12390.46,2726.92 h60
  text "ENEPIG" at 13728,2723.64 h60
  text "SURFACE FINISH:" at 11329.46,2722.64 h60
  text "X" at 12203.51,2722.64 h60
  text "IMM. TIN/SILVER OR EQUIV" at 11659,2565.64 h60
  text "OTHER" at 13090.46,2565.64 h60
  text "ARRAY/PANEL:" at 11329.46,2386.64 h60
  text "CUT AND TRIM PER M1 BOARD OUTLINE" at 12390.46,2382.35 h60
  text "N.C. ROUTE" at 12390.46,2230.64 h60
  text "X" at 13069.46,2230.64 h60
  text "V. SCORE" at 13256.46,2230.64 h60
  text "CERTIFICATION:" at 11329.46,2093.64 h60
  text "MATERIALS AND WORKMANSHIP FOR ALL PCBS" at 12054.46,2093.64 h60
  text "TO MEET OR EXCEED THE REQUIREMENTS OF:" at 12054.46,1995.64 h60
  text "X" at 11680.96,1859.13 h60
  text "ANSI IPC-A-600F CLASS ->" at 11819.96,1859.13 h60
  text "X" at 13459.02,1859.13 h60
  text "2" at 13577.96,1859.14 h60
  text "1" at 13262.96,1857.64 h60
  text "3" at 13931.96,1857.64 h60
  text "X" at 12495.02,1699.64 h60
  text "RoHS" at 12631.96,1699.64 h60
  text "OTHER" at 13276.36,1699.64 h60
  text "PER ORDER" at 13673.42,1699.64 h60
  text "ALL BOARDS MUST MEET OR EXCEED UL94-V0 REQUIREMENTS." at 11357,1534 h60
  text "PCB MUST BEAR THE UL94V-0 UL REGISTERED MATERIAL ID NUMBER" at 11357,1414 h60
  text "ADDITIONAL REQUIREMENTS:" at 11329.46,1240.64 h60
  text "MICROSECTION:" at 11404.23,1125.64 h60
  text "YES" at 12309.96,1125.64 h60
  text "REQUIRED" at 13171.46,969.49 h60
  text "BARE BOARD ELEC. TEST:" at 11404.23,966.64 h60
  text "NONE" at 12709.96,966.64 h60
  text "X" at 13044.46,966.64 h60
  text "PER ORDER" at 13763.46,966.64 h60
  text ".Layer_Name" at 577,-858.49 h60
M11 Gerber Information:
  lines w10: -292,-930.17 6308,-930.17 ; -292,-726.83 6310,-726.83 ; -292,-523.5 -292,-1133.5 3713,-1133.5 6310,-1133.5 6310,-523.5 -291.5,-523.5 -291.5,-1133.5 1284,-1133.5 ; 2173,-1133.5 2173,-523.5 ; 3440,-726.83 3440,-523.5 ; 4280,-726.83 4280,-523.5 ; 4902,-1140 4902,-937.17
  text "ALL ARTWORK VIEWED FROM TOP SIDE" at -228.5,-655.67 h60
  text "BOARD #:" at 2248,-655.67 h60
  text ".PRJ_Number" at 2793.5,-655.67 h60
  text "REV:" at 3638,-655.67 h60
  text ".PCB_Rev" at 3929.5,-655.67 h60
  text "SVN REV:" at 4476,-655.67 h60
  text ".VersionControl_RevNumber" at 4982,-655.67 h60
  text "LAYER NAME =" at -228.5,-858.49 h60
  text "TID #:" at 2248,-859 h60
  text ".TID" at 2793.5,-859 h60
  text "PLOT NAME =" at -228.5,-1064.34 h60
  text ".plot_File_Name" at 577,-1064.34 h60
  text "GENERATED    :" at 2250,-1064.34 h60
  text ".Print_Date" at 3119.5,-1064.34 h60
  text ".Print_Time" at 3848.5,-1064.34 h60
  text "TEXAS INSTRUMENTS" at 5113,-1064.34 h60
M12 Stackup:
  drawing of 399 lines, arcs and shapes, not listed
  text "Layer" at 10537.5,7857.5 h50
  text "Name" at 10882.43,7857.5 h50
  text "Material" at 11668.88,7857.5 h50
  text "Thickness" at 12388.68,7857.5 h50
  text "Constant" at 12933.55,7857.5 h50
  text "Board Layer Stack" at 13411.76,7857.5 h50
  text "1" at 10537.5,7757.5 h50
  text "Top Overlay" at 10882.43,7757.5 h50
  text "2" at 10537.5,7657.5 h50
  text "Top Solder" at 10882.43,7657.5 h50
  text "Solder Resist" at 11668.88,7657.5 h50
  text "0.40mil" at 12388.68,7657.5 h50
  text "3.5" at 12933.55,7657.5 h50
  text "3" at 10537.5,7557.5 h50
  text "Top Layer" at 10882.43,7557.5 h50
  text "Copper" at 11668.88,7557.5 h50
  text "1.40mil" at 12388.68,7557.5 h50
  text "4" at 10537.5,7457.5 h50
  text "Dielectric1" at 10882.43,7457.5 h50
  text "FR-4 High TG" at 11668.88,7457.5 h50
  text "4.80mil" at 12388.68,7457.5 h50
  text "4.8" at 12933.55,7457.5 h50
  text "5" at 10537.5,7357.5 h50
  text "Signal Layer 1" at 10882.43,7357.5 h50
  text "Copper" at 11668.88,7357.5 h50
  text "1.40mil" at 12388.68,7357.5 h50
  text "6" at 10537.5,7257.5 h50
  text "Dielectric 2" at 10882.43,7257.5 h50
  text "FR-4 High TG" at 11668.88,7257.5 h50
  text "4.80mil" at 12388.68,7257.5 h50
  text "4.8" at 12933.55,7257.5 h50
  text "7" at 10537.5,7157.5 h50
  text "Signal Layer 2" at 10882.43,7157.5 h50
  text "Copper" at 11668.88,7157.5 h50
  text "1.40mil" at 12388.68,7157.5 h50
  text "8" at 10537.5,7057.5 h50
  text "Dielectric 3" at 10882.43,7057.5 h50
  text "FR-4 High TG" at 11668.88,7057.5 h50
  text "4.80mil" at 12388.68,7057.5 h50
  text "4.8" at 12933.55,7057.5 h50
  text "9" at 10537.5,6957.5 h50
  text "Signal Layer 3" at 10882.43,6957.5 h50
  text "Copper" at 11668.88,6957.5 h50
  text "1.40mil" at 12388.68,6957.5 h50
  text "10" at 10537.5,6857.5 h50
  text "Dielectric 4" at 10882.43,6857.5 h50
  text "FR-4 High TG" at 11668.88,6857.5 h50
  text "4.80mil" at 12388.68,6857.5 h50
  text "4.8" at 12933.55,6857.5 h50
  text "11" at 10537.5,6757.5 h50
  text "Signal Layer 4" at 10882.43,6757.5 h50
  text "Copper" at 11668.88,6757.5 h50
  text "1.40mil" at 12388.68,6757.5 h50
  text "12" at 10537.5,6657.5 h50
  text "Dielectric 5" at 10882.43,6657.5 h50
  text "FR-4 High TG" at 11668.88,6657.5 h50
  text "4.80mil" at 12388.68,6657.5 h50
  text "4.8" at 12933.55,6657.5 h50
  text "13" at 10537.5,6557.5 h50
  text "Bottom Layer" at 10882.43,6557.5 h50
  text "Copper" at 11668.88,6557.5 h50
  text "1.40mil" at 12388.68,6557.5 h50
  text "14" at 10537.5,6457.5 h50
  text "Bottom Solder" at 10882.43,6457.5 h50
  text "Solder Resist" at 11668.88,6457.5 h50
  text "0.40mil" at 12388.68,6457.5 h50
  text "4.8" at 12933.55,6457.5 h50
  text "15" at 10537.5,6357.5 h50
  text "Bottom Overlay" at 10882.43,6357.5 h50
  text ".Layer_Name" at 577,-858.49 h60
M13 Component Bodies Top:
  text ".Layer_Name" at 577,-858.49 h60
M14 Component Bodies Bottom:
  text ".Layer_Name" at 577,-858.49 h60
M15 Courtyards Top:
  text ".Layer_Name" at 577,-858.49 h60
M16 Courtyards Bottom:
  text ".Layer_Name" at 577,-858.49 h60
Drill Drawing:
  circle w10: c545.62,5217.27 r20
  circle w10: c545.62,5217.27 r33.33
  lines w10: 512.29,4733.94 545.62,4750.61 578.96,4733.94 562.29,4767.27 578.96,4800.61 545.62,4783.94 512.29,4800.61 528.96,4767.27 512.29,4733.94 ; 512.29,4950.61 578.96,4950.61 545.62,4883.94 512.29,4950.61 ; 512.29,5050.61 528.96,5050.61 545.62,5033.94 562.29,5050.61 578.96,5050.61 562.29,5067.27 578.96,5083.94 562.29,5083.94 545.62,5100.61 528.96,5083.94 512.29,5083.94 528.96,5067.27 512.29,5050.61 ; 512.29,5333.94 578.96,5333.94 578.96,5400.61 512.29,5400.61 512.29,5333.94 ; 512.29,5500.61 528.96,5500.61 528.96,5483.94 562.29,5483.94 562.29,5500.61 578.96,5500.61 578.96,5533.94 562.29,5533.94 562.29,5550.61 528.96,5550.61 528.96,5533.94 512.29,5533.94 512.29,5500.61 ; 512.29,5783.94 512.29,5800.61 528.96,5817.27 512.29,5833.94 512.29,5850.61 528.96,5850.61 545.62,5833.94 562.29,5850.61 578.96,5850.61 578.96,5833.94 562.29,5817.27 578.96,5800.61 578.96,5783.94 562.29,5783.94 545.62,5800.61 528.96,5783.94 512.29,5783.94 ; 512.29,5933.94 578.96,5933.94 578.96,6000.61 512.29,6000.61 512.29,5933.94 ; 525.62,4747.27 545.62,4757.27 565.62,4747.27 555.62,4767.27 565.62,4787.27 545.62,4777.27 525.62,4787.27 535.62,4767.27 525.62,4747.27 ; 525.62,4937.27 565.62,4937.27 545.62,4897.27 525.62,4937.27 ; 525.62,5057.27 535.62,5057.27 545.62,5047.27 555.62,5057.27 565.62,5057.27 555.62,5067.27 565.62,5077.27 555.62,5077.27 545.62,5087.27 535.62,5077.27 525.62,5077.27 535.62,5067.27 525.62,5057.27 ; 525.62,5507.27 535.62,5507.27 535.62,5497.27 555.62,5497.27 555.62,5507.27 565.62,5507.27 565.62,5527.27 555.62,5527.27 555.62,5537.27 535.62,5537.27 535.62,5527.27 525.62,5527.27 525.62,5507.27 ; 525.62,5797.27 525.62,5807.27 535.62,5817.27 525.62,5827.27 525.62,5837.27 535.62,5837.27 545.62,5827.27 555.62,5837.27 565.62,5837.27 565.62,5827.27 555.62,5817.27 565.62,5807.27 565.62,5797.27 555.62,5797.27 545.62,5807.27 535.62,5797.27 525.62,5797.27 ; 525.62,5947.27 565.62,5947.27 565.62,5987.27 525.62,5987.27 525.62,5947.27
  lines w15: 452.5,4688.94 10459.71,4688.94 ; 452.5,7088.94 10459.71,7088.94 ; 1003.38,4538.94 1003.38,7238.94 ; 1593.22,4538.94 1593.22,7238.94 ; 2742.88,4538.94 2742.88,7238.94 ; 3248.76,4538.94 3248.76,7238.94 ; 3982.56,4538.94 3982.56,7238.94 ; 5482.11,4538.94 5482.11,7238.94 ; 6071.96,4538.94 6071.96,7238.94 ; 6817.76,4538.94 6817.76,7238.94 ; 7987.42,4538.94 7987.42,7238.94 ; 9057.11,4538.94 9057.11,7238.94 ; 452.5,4538.94 10459.71,4538.94 10459.71,7238.94 452.5,7238.94 452.5,4538.94
  text "Symbol" at 542.5,7133.94 h72
  text "Count" at 1048.38,7133.94 h72
  text "Hole Size" at 1638.22,7133.94 h72
  text "Plated" at 2787.88,7133.94 h72
  text "Hole Type" at 3293.76,7133.94 h72
  text "Drill Layer Pair" at 4027.56,7133.94 h72
  text "Via/Pad" at 5527.11,7133.94 h72
  text "Pad Shape" at 6116.96,7133.94 h72
  text "Template" at 6862.76,7133.94 h72
  text "Hole Length" at 8032.42,7133.94 h72
  text "Routed Path Length" at 9102.11,7133.94 h72
  text "2" at 1048.38,6983.94 h60
  text "19.69mil (0.500mm)" at 1638.22,6983.94 h60
  text "PTH" at 2787.88,6983.94 h60
  text "Slot" at 3293.76,6983.94 h60
  text "Top Layer - Bottom Layer" at 4027.56,6983.94 h60
  text "Pad" at 5527.11,6983.94 h60
  text "Rounded" at 6116.96,6983.94 h60
  text "r110_165h50_110r100" at 6862.76,6983.94 h60
  text "43.11mil (1.095mm)" at 8032.42,6983.94 h60
  text "23.43mil (0.595mm)" at 9102.11,6983.94 h60
  text "F" at 513.41,6973.95 h66.67
  text "2" at 1048.38,6833.94 h60
  text "19.69mil (0.500mm)" at 1638.22,6833.94 h60
  text "PTH" at 2787.88,6833.94 h60
  text "Slot" at 3293.76,6833.94 h60
  text "Top Layer - Bottom Layer" at 4027.56,6833.94 h60
  text "Pad" at 5527.11,6833.94 h60
  text "Rounded" at 6116.96,6833.94 h60
  text "r110_170h50_110r100" at 6862.76,6833.94 h60
  text "43.31mil (1.100mm)" at 8032.42,6833.94 h60
  text "23.62mil (0.600mm)" at 9102.11,6833.94 h60
  text "E" at 513.41,6823.95 h66.67
  text "2" at 1048.38,6683.94 h60
  text "25.59mil (0.650mm)" at 1638.22,6683.94 h60
  text "PTH" at 2787.88,6683.94 h60
  text "Round" at 3293.76,6683.94 h60
  text "Top Layer - Bottom Layer" at 4027.56,6683.94 h60
  text "Pad" at 5527.11,6683.94 h60
  text "Rounded" at 6116.96,6683.94 h60
  text "c155h65" at 6862.76,6683.94 h60
  text "-" at 8032.42,6683.94 h60
  text "-" at 9102.11,6683.94 h60
  text "G" at 513.41,6673.95 h66.67
  text "4" at 1048.38,6533.94 h60
  text "125.98mil (3.200mm)" at 1638.22,6533.94 h60
  text "PTH" at 2787.88,6533.94 h60
  text "Round" at 3293.76,6533.94 h60
  text "Top Layer - Bottom Layer" at 4027.56,6533.94 h60
  text "Pad" at 5527.11,6533.94 h60
  text "Rounded" at 6116.96,6533.94 h60
  text "c800h320" at 6862.76,6533.94 h60
  text "-" at 8032.42,6533.94 h60
  text "-" at 9102.11,6533.94 h60
  text "B" at 513.41,6523.95 h66.67
  text "6" at 1048.38,6383.94 h60
  text "43.31mil (1.100mm)" at 1638.22,6383.94 h60
  text "PTH" at 2787.88,6383.94 h60
  text "Round" at 3293.76,6383.94 h60
  text "Top Layer - Bottom Layer" at 4027.56,6383.94 h60
  text "Pad" at 5527.11,6383.94 h60
  text "(Mixed)" at 6116.96,6383.94 h60
  text "(Mixed)" at 6862.76,6383.94 h60
  text "-" at 8032.42,6383.94 h60
  text "-" at 9102.11,6383.94 h60
  text "C" at 513.41,6373.95 h66.67
  text "8" at 1048.38,6233.94 h60
  text "44.88mil (1.140mm)" at 1638.22,6233.94 h60
  text "PTH" at 2787.88,6233.94 h60
  text "Round" at 3293.76,6233.94 h60
  text "Top Layer - Bottom Layer" at 4027.56,6233.94 h60
  text "Pad" at 5527.11,6233.94 h60
  text "(Mixed)" at 6116.96,6233.94 h60
  text "(Mixed)" at 6862.76,6233.94 h60
  text "-" at 8032.42,6233.94 h60
  text "-" at 9102.11,6233.94 h60
  text "H" at 513.41,6223.95 h66.67
  text "9" at 1048.38,6083.94 h60
  text "29.53mil (0.750mm)" at 1638.22,6083.94 h60
  text "PTH" at 2787.88,6083.94 h60
  text "Round" at 3293.76,6083.94 h60
  text "Top Layer - Bottom Layer" at 4027.56,6083.94 h60
  text "Pad" at 5527.11,6083.94 h60
  text "(Mixed)" at 6116.96,6083.94 h60
  text "(Mixed)" at 6862.76,6083.94 h60
  text "-" at 8032.42,6083.94 h60
  text "-" at 9102.11,6083.94 h60
  text "D" at 513.41,6073.95 h66.67
  text "24" at 1048.38,5933.94 h60
  text "7.87mil (0.200mm)" at 1638.22,5933.94 h60
  text "PTH" at 2787.88,5933.94 h60
  text "Round" at 3293.76,5933.94 h60
  text "Top Layer - Bottom Layer" at 4027.56,5933.94 h60
  text "Via" at 5527.11,5933.94 h60
  text "Rounded" at 6116.96,5933.94 h60
  text "(Mixed)" at 6862.76,5933.94 h60
  text "-" at 8032.42,5933.94 h60
  text "-" at 9102.11,5933.94 h60
  text "32" at 1048.38,5783.94 h60
  text "40.16mil (1.020mm)" at 1638.22,5783.94 h60
  text "PTH" at 2787.88,5783.94 h60
  text "Round" at 3293.76,5783.94 h60
  text "Top Layer - Bottom Layer" at 4027.56,5783.94 h60
  text "Pad" at 5527.11,5783.94 h60
  text "(Mixed)" at 6116.96,5783.94 h60
  text "(Mixed)" at 6862.76,5783.94 h60
  text "-" at 8032.42,5783.94 h60
  text "-" at 9102.11,5783.94 h60
  text "36" at 1048.38,5633.94 h60
  text "12.00mil (0.305mm)" at 1638.22,5633.94 h60
  text "PTH" at 2787.88,5633.94 h60
  text "Round" at 3293.76,5633.94 h60
  text "Top Layer - Bottom Layer" at 4027.56,5633.94 h60
  text "Via" at 5527.11,5633.94 h60
  text "Rounded" at 6116.96,5633.94 h60
  text "v71h30m0mx0" at 6862.76,5633.94 h60
  text "-" at 8032.42,5633.94 h60
  text "-" at 9102.11,5633.94 h60
  text "A" at 513.41,5623.95 h66.67
  text "37" at 1048.38,5483.94 h60
  text "8.00mil (0.203mm)" at 1638.22,5483.94 h60
  text "PTH" at 2787.88,5483.94 h60
  text "Round" at 3293.76,5483.94 h60
  text "Top Layer - Bottom Layer" at 4027.56,5483.94 h60
  text "Via" at 5527.11,5483.94 h60
  text "Rounded" at 6116.96,5483.94 h60
  text "v46h20m0mx0" at 6862.76,5483.94 h60
  text "-" at 8032.42,5483.94 h60
  text "-" at 9102.11,5483.94 h60
  text "40" at 1048.38,5333.94 h60
  text "73.00mil (1.854mm)" at 1638.22,5333.94 h60
  text "PTH" at 2787.88,5333.94 h60
  text "Round" at 3293.76,5333.94 h60
  text "Top Layer - Bottom Layer" at 4027.56,5333.94 h60
  text "Pad" at 5527.11,5333.94 h60
  text "Rounded" at 6116.96,5333.94 h60
  text "c305h185" at 6862.76,5333.94 h60
  text "-" at 8032.42,5333.94 h60
  text "-" at 9102.11,5333.94 h60
  text "48" at 1048.38,5183.94 h60
  text "63.00mil (1.600mm)" at 1638.22,5183.94 h60
  text "PTH" at 2787.88,5183.94 h60
  text "Round" at 3293.76,5183.94 h60
  text "Top Layer - Bottom Layer" at 4027.56,5183.94 h60
  text "Pad" at 5527.11,5183.94 h60
  text "Rounded" at 6116.96,5183.94 h60
  text "c221h160" at 6862.76,5183.94 h60
  text "-" at 8032.42,5183.94 h60
  text "-" at 9102.11,5183.94 h60
  text "74" at 1048.38,5033.94 h60
  text "6.00mil (0.152mm)" at 1638.22,5033.94 h60
  text "PTH" at 2787.88,5033.94 h60
  text "Round" at 3293.76,5033.94 h60
  text "Top Layer - Bottom Layer" at 4027.56,5033.94 h60
  text "Via" at 5527.11,5033.94 h60
  text "Rounded" at 6116.96,5033.94 h60
  text "(Mixed)" at 6862.76,5033.94 h60
  text "-" at 8032.42,5033.94 h60
  text "-" at 9102.11,5033.94 h60
  text "78" at 1048.38,4883.94 h60
  text "40.00mil (1.016mm)" at 1638.22,4883.94 h60
  text "PTH" at 2787.88,4883.94 h60
  text "Round" at 3293.76,4883.94 h60
  text "Top Layer - Bottom Layer" at 4027.56,4883.94 h60
  text "Pad" at 5527.11,4883.94 h60
  text "(Mixed)" at 6116.96,4883.94 h60
  text "(Mixed)" at 6862.76,4883.94 h60
  text "-" at 8032.42,4883.94 h60
  text "-" at 9102.11,4883.94 h60
  text "399" at 1048.38,4733.94 h60
  text "10.00mil (0.254mm)" at 1638.22,4733.94 h60
  text "PTH" at 2787.88,4733.94 h60
  text "Round" at 3293.76,4733.94 h60
  text "Top Layer - Bottom Layer" at 4027.56,4733.94 h60
  text "Via" at 5527.11,4733.94 h60
  text "Rounded" at 6116.96,4733.94 h60
  text "v56h25m0mx0" at 6862.76,4733.94 h60
  text "-" at 8032.42,4733.94 h60
  text "-" at 9102.11,4733.94 h60
  text "801 Total" at 1048.38,4583.94 h60
  text "Slot definitions :" at 542.5,4438.97 h60
  text "Routed Path Length" at 1575.19,4438.97 h60
  text "= Calculated from tool start centre position to tool end centre position." at 2677.86,4438.97 h60
  text "Hole Length" at 1575.19,4338.99 h60
  text "= Routed Path Length + Tool Size = Slot length as defined in the PCB layout" at 2267.99,4338.99 h60
  text "All 6 MIL-holed vias must be filled and plated over" at 560,4240 h60
  text ".Layer_Name" at 577,-858.49 h60
M17 Embedded Cavity:
  text ".Layer_Name" at 577,-858.49 h60
M18 Embedded Assembly:
  text ".Layer_Name" at 577,-858.49 h60
M19 Embedded Keepout:
  text ".Layer_Name" at 577,-858.49 h60

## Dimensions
0,-400 to 1000,-400 on M2 Board Dimensions
0,0 to 6500,0 on M2 Board Dimensions
0,0 to 0,3500 on M2 Board Dimensions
